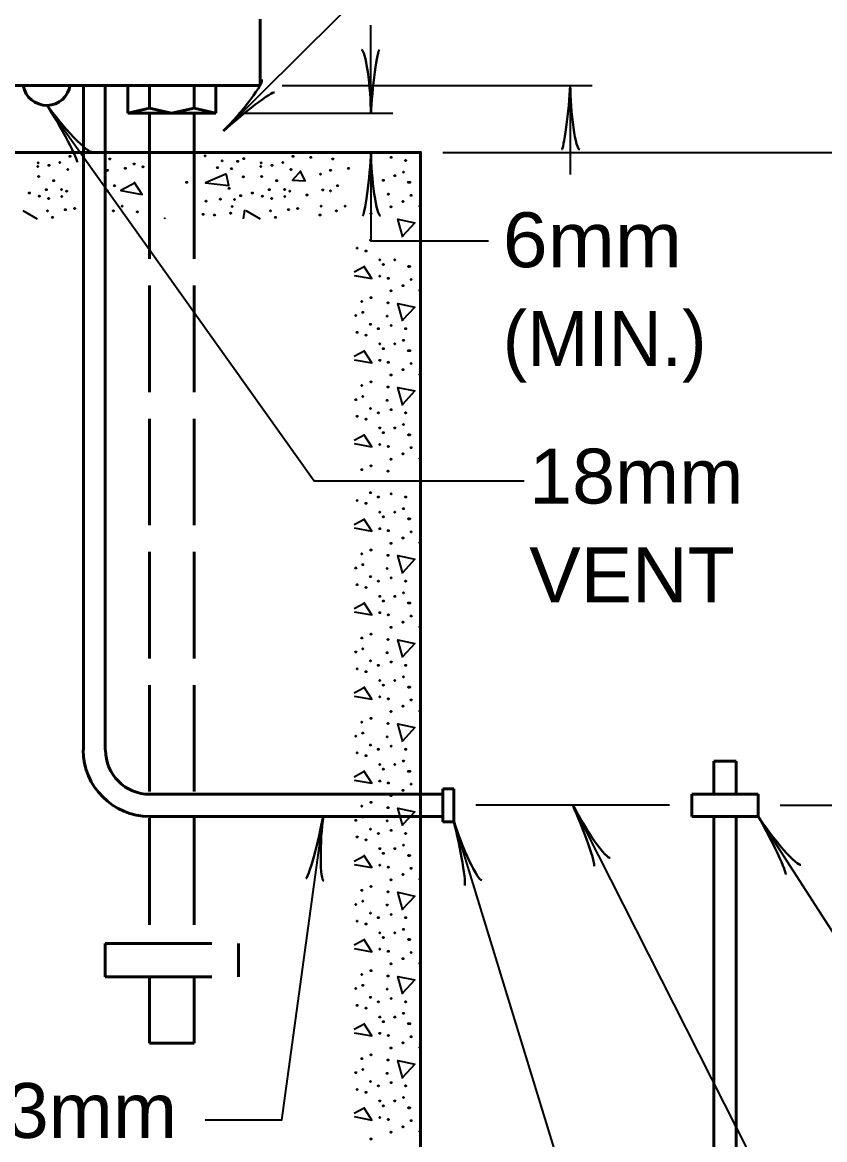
# Model space of a CAD drawing. Extents: x -39 to 816, y -16 to 528.
# Drawn here: x 272.5 to 316.4, y 202.8 to 263.8 of the extents above; entities that cross this region are included whole.
import ezdxf

# ---------------------------------------------------------------- set-up
doc = ezdxf.new("R2010")
doc.units = 0
doc.header["$LTSCALE"] = 0.97
doc.linetypes.add('LONG_DASHED', pattern=[7.5, 6, -1.5])
doc.layers.add('1', color=7, linetype='Continuous', lineweight=35)

msp = doc.modelspace()

# ---------------------------------------------------------------- linework, layer by layer
at = {"layer": '1', "lineweight": 53}
for p, q in [((285.5174, 263.9716), (285.5174, 260.3476)), ((258.3014, 260.3476), (285.5174, 260.3476)), ((275.8454, 260.3476), (275.8454, 224.0596)), ((277.0454, 260.3476), (277.0454, 224.0596)), ((278.2694, 260.3476), (278.2694, 258.8356)), ((279.4694, 260.3476), (279.4694, 259.1236)), ((281.8934, 260.3476), (281.8934, 259.1236)), ((283.0934, 260.3476), (283.0934, 258.8356)), ((278.2694, 258.8356), (279.4694, 259.1236)), ((278.2694, 258.8356), (283.0934, 258.8356)), ((280.6694, 258.8356), (279.4694, 259.1236)), ((279.4694, 258.8356), (279.4694, 256.6996)), ((280.6694, 258.8356), (281.8934, 259.1236)), ((283.0934, 258.8356), (281.8934, 259.1236)), ((281.8934, 258.8356), (281.8934, 256.6996)), ((310.3094, 223.4356), (311.5334, 223.4356)), ((310.3094, 223.4356), (310.3094, 221.6356)), ((311.5334, 223.4356), (311.5334, 221.6356)), ((279.4694, 221.6356), (295.5014, 221.6356)), ((295.5014, 221.9236), (295.5014, 220.1236)), ((295.5014, 221.9236), (296.1014, 221.9236)), ((296.1014, 221.9236), (296.1014, 220.1236)), ((309.1094, 220.4116), (309.1094, 221.6356)), ((309.1094, 221.6356), (312.7334, 221.6356)), ((312.7334, 220.4116), (312.7334, 221.6356)), ((279.4694, 220.4116), (295.5014, 220.4116)), ((309.1094, 220.4116), (312.7334, 220.4116)), ((310.3094, 220.4116), (310.3094, 170.2276)), ((311.5334, 220.4116), (311.5334, 169.6276)), ((295.5014, 220.1236), (296.1014, 220.1236))]:
    msp.add_line(p, q, dxfattribs=at)
at = {"layer": '1'}
for p, q in [((291.5654, 258.8356), (291.5654, 263.6596)), ((286.7174, 260.3476), (303.6614, 260.3476)), ((302.4614, 260.3476), (302.4614, 255.4996)), ((284.3174, 258.8356), (292.7654, 258.8356)), ((281.1254, 256.6756), (281.1014, 256.6996)), ((291.5654, 256.6996), (291.5654, 251.8756)), ((293.3174, 256.6756), (293.2934, 256.6996)), ((295.5014, 256.6996), (324.2451, 256.6996)), ((272.5334, 253.5316), (273.3254, 253.0756)), ((284.6054, 253.0756), (284.6774, 253.5556)), ((284.7254, 253.5316), (285.5174, 253.0756)), ((291.5654, 251.8756), (297.9974, 251.8756)), ((291.2294, 250.4596), (290.6534, 250.1476)), ((291.2294, 245.8516), (290.6534, 245.5396)), ((291.2294, 241.2676), (290.6534, 240.9556)), ((291.2294, 236.6596), (290.6534, 236.3476)), ((291.2294, 232.0756), (290.6534, 231.7636)), ((291.2294, 227.4676), (290.6534, 227.1556)), ((291.2294, 222.8836), (290.6534, 222.5716)), ((307.8854, 221.0356), (297.3014, 221.0356)), ((313.9334, 221.0356), (324.2451, 221.0356)), ((291.2294, 218.2756), (290.6534, 217.9636)), ((291.2294, 213.6916), (290.6534, 213.3796)), ((291.2294, 209.0836), (290.6534, 208.7716)), ((291.2294, 204.4996), (290.6534, 204.1876))]:
    msp.add_line(p, q, dxfattribs=at)
at = {"layer": '1', "linetype": 'LONG_DASHED', "lineweight": 53}
for p, q in [((279.4694, 256.6996), (279.4694, 213.4756)), ((281.8934, 256.6996), (281.8934, 213.4756)), ((277.0454, 213.4756), (284.3174, 213.4756)), ((277.0454, 213.4756), (277.0454, 211.6516)), ((284.3174, 213.4756), (284.3174, 211.6516)), ((277.0454, 211.6516), (284.3174, 211.6516)), ((279.4694, 211.6516), (279.4694, 208.0276)), ((281.8934, 211.6516), (281.8934, 208.0276)), ((279.4694, 208.0276), (281.8934, 208.0276))]:
    msp.add_line(p, q, dxfattribs=at)
at = {"layer": '1'}
for points in [[(283.5072, 257.8762), (300.1083, 274.3443), (323.9155, 274.3443)], [(273.8534, 259.2676), (288.4694, 238.7476), (299.9414, 238.7476)], [(283.6694, 255.5236), (282.5174, 255.0436), (283.7894, 254.8996), (283.6694, 255.4756)], [(287.7254, 255.6916), (287.2694, 255.1876), (287.9654, 255.1396), (287.7254, 255.6436)], [(278.6774, 255.0436), (277.8854, 254.6116), (279.0614, 254.3956), (278.6294, 255.0676)], [(293.3174, 252.0676), (293.0294, 253.0516), (293.9654, 252.8596), (293.2934, 252.1156)], [(290.6534, 249.9796), (291.6134, 249.8116), (291.1814, 250.4836)], [(293.3174, 247.4836), (293.0294, 248.4436), (293.9654, 248.2516), (293.2934, 247.5316)], [(290.6534, 245.3716), (291.6134, 245.2036), (291.1814, 245.8756)], [(293.3174, 242.8756), (293.0294, 243.8596), (293.9654, 243.6676), (293.2934, 242.9236)], [(290.6534, 240.7876), (291.6134, 240.6196), (291.1814, 241.2916)], [(290.6534, 236.1796), (291.6134, 236.0116), (291.1814, 236.6836)], [(293.3174, 233.6836), (293.0294, 234.6676), (293.9654, 234.4756), (293.2934, 233.7316)], [(290.6534, 231.5956), (291.6134, 231.4276), (291.1814, 232.0996)], [(293.3174, 229.0996), (293.0294, 230.0596), (293.9654, 229.8676), (293.2934, 229.1476)], [(290.6534, 226.9876), (291.6134, 226.8196), (291.1814, 227.4916)], [(293.3174, 224.4916), (293.0294, 225.4756), (293.9654, 225.2836), (293.2934, 224.5396)], [(290.6534, 222.4036), (291.6134, 222.2356), (291.1814, 222.9076)], [(302.6054, 221.0356), (316.3814, 193.8676), (326.9174, 193.8676)], [(288.9494, 220.4116), (286.6694, 203.8276), (282.4957, 203.8276)], [(293.3174, 219.9076), (293.0294, 220.8676), (293.9654, 220.6756), (293.2934, 219.9556)], [(312.7334, 220.4116), (320.5574, 208.2916), (326.9174, 208.2916)], [(296.1014, 220.1236), (307.2854, 183.6196), (326.9174, 183.6196)], [(290.6534, 217.7956), (291.6134, 217.6276), (291.1814, 218.2996)], [(293.3174, 215.2996), (293.0294, 216.2836), (293.9654, 216.0676), (293.2934, 215.3476)], [(290.6534, 213.2116), (291.6134, 213.0196), (291.1814, 213.7156)], [(293.3174, 210.7156), (293.0294, 211.6756), (293.9654, 211.4836), (293.2934, 210.7636)], [(290.6534, 208.6036), (291.6134, 208.4356), (291.1814, 209.1076)], [(293.3174, 206.1076), (293.0294, 207.0916), (293.9654, 206.8756), (293.2934, 206.1556)], [(290.6534, 204.0196), (291.6134, 203.8276), (291.1814, 204.5236)]]:
    msp.add_lwpolyline(points, dxfattribs=at)
at = {"layer": '1', "lineweight": 53}
msp.add_lwpolyline([(249.5414, 182.9236), (249.5414, 256.6996), (294.2774, 256.6996), (294.2774, 179.2996)], dxfattribs=at)
at = {"layer": '1'}
for centre in [(275.1113, 256.4824), (282.5016, 256.5145), (287.3041, 256.4824), (288.282, 256.4343), (292.6745, 256.4343), (273.3547, 255.927), (273.3708, 256.1296), (273.9639, 255.9911), (274.557, 256.1456), (274.9991, 255.7666), (277.2916, 256.3381), (278.1412, 255.8308), (278.6221, 256.0655), (279.103, 255.9109), (283.1749, 255.8629), (283.4314, 256.2419), (283.9444, 255.8147), (284.2811, 256.2098), (284.6177, 256.354), (285.5475, 255.927), (285.5635, 256.1296), (286.1566, 255.9911), (286.7498, 256.1456), (287.1919, 255.7666), (289.4843, 256.3381), (290.334, 255.8308), (293.46, 256.2578), (273.4028, 255.3818), (274.2204, 255.1573), (277.1633, 255.7185), (284.5856, 255.3657), (285.5956, 255.3818), (286.4132, 255.1573), (288.811, 255.5101), (289.3561, 255.7185), (292.2416, 255.1733), (292.8668, 255.4299), (293.3478, 255.6224), (273.8196, 254.6602), (274.6533, 254.6762), (274.935, 254.58), (277.1633, 254.596), (277.548, 254.8847), (281.4917, 255.0611), (283.8161, 254.7403), (286.0123, 254.6602), (286.846, 254.6762), (287.1278, 254.58), (288.9392, 254.6441), (289.3561, 254.596), (289.7408, 254.8847), (293.6203, 255.0611), (293.6844, 255.0611), (272.8898, 254.4838), (273.4349, 254.3074), (273.9479, 254.179), (274.6692, 254.2913), (282.5497, 254.0348), (283.3352, 254.147), (284.1047, 254.131), (284.4413, 254.3394), (285.0825, 254.4838), (285.6277, 254.3074), (286.1407, 254.179), (286.862, 254.2913), (288.0735, 254.3715), (292.5141, 254.4197), (293.3157, 254.0187), (293.7646, 254.3554), (273.8837, 253.5056), (274.8617, 253.5697), (275.3678, 253.6338), (277.4839, 253.5056), (277.9648, 253.7622), (278.7978, 253.4501), (282.3894, 253.3132), (283.8963, 253.3773), (283.9765, 253.7461), (286.0765, 253.5056), (287.0544, 253.5697), (287.5605, 253.6338), (288.843, 253.7622), (289.6767, 253.5056), (290.1576, 253.7622), (291.5683, 253.3612), (292.6584, 253.73), (294.2455, 253.7622), (274.1563, 253.1527), (283.0145, 253.2811), (286.3491, 253.1527), (288.779, 253.2811), (291.5363, 251.9019), (290.8149, 251.469), (291.2958, 251.3144), (292.0492, 250.8334), (292.2416, 250.5768), (292.8668, 250.8334), (293.6203, 250.4646), (293.6844, 250.4646), (292.0493, 249.9353), (292.5141, 249.8232), (293.7646, 249.759), (292.6584, 249.1336), (293.3157, 249.4222), (294.2455, 249.1657), (291.0713, 248.5562), (291.5683, 248.7647), (292.4981, 248.4761), (291.1195, 247.963), (290.7347, 247.7866), (291.5363, 247.3055), (292.45, 247.7545), (292.6745, 247.2414), (290.8149, 246.8725), (291.2958, 246.718), (291.9691, 247.0649), (293.46, 247.0649), (292.0492, 246.237), (292.8668, 246.237), (293.3478, 246.4294), (292.2416, 245.9803), (293.6203, 245.8681), (293.6844, 245.8681), (292.0493, 245.3389), (292.5141, 245.2267), (293.3157, 244.8258), (293.7646, 245.1625), (291.5683, 244.1683), (292.6584, 244.5371), (294.2455, 244.5692), (291.0713, 243.9598), (292.4981, 243.8796), (290.7347, 243.1901), (291.1195, 243.3665), (292.45, 243.158), (291.5363, 242.709), (291.9691, 242.4684), (292.6745, 242.6449), (293.46, 242.4684), (290.8149, 242.276), (291.2958, 242.1215), (293.3478, 241.8329), (292.0492, 241.6405), (292.2416, 241.3838), (292.8668, 241.6405), (293.6203, 241.2717), (293.6844, 241.2717), (292.0493, 240.7424), (292.5141, 240.6302), (293.7646, 240.566), (292.6584, 239.9406), (293.3157, 240.2293), (294.2455, 239.9727), (291.0713, 239.3633), (291.5683, 239.5718), (292.4981, 239.2831), (291.5363, 238.1125), (292.6745, 238.0484), (290.8149, 237.6796), (291.2958, 237.525), (291.9691, 237.8719), (293.46, 237.8719), (292.0492, 237.044), (292.8668, 237.044), (293.3478, 237.2364), (292.2416, 236.7873), (293.6203, 236.6752), (293.6844, 236.6752), (292.0493, 236.1459), (292.5141, 236.0337), (293.3157, 235.6328), (293.7646, 235.9695), (292.6584, 235.3441), (294.2455, 235.3762), (291.0713, 234.7668), (291.5683, 234.9753), (292.4981, 234.6866), (290.7347, 233.9971), (291.1195, 234.1735), (292.45, 233.965), (291.5363, 233.516), (291.9691, 233.2754), (292.6745, 233.4519), (293.46, 233.2754), (290.8149, 233.0831), (291.2958, 232.9285), (293.3478, 232.64), (292.0492, 232.4475), (292.2416, 232.1909), (292.8668, 232.4475), (293.6203, 232.0787), (293.6844, 232.0787), (292.0493, 231.5494), (292.5141, 231.4373), (293.7646, 231.373), (292.6584, 230.7476), (293.3157, 231.0363), (294.2455, 230.7798), (291.0713, 230.1703), (291.5683, 230.3788), (291.1195, 229.577), (292.4981, 230.0902), (290.7347, 229.4007), (291.5363, 228.9195), (292.45, 229.3685), (290.8149, 228.4866), (291.2958, 228.332), (291.9691, 228.6789), (292.6745, 228.8554), (293.46, 228.6789), (292.0492, 227.851), (292.8668, 227.851), (293.3478, 228.0435), (292.2416, 227.5944), (293.6203, 227.4822), (293.6844, 227.4822), (292.0493, 226.9529), (292.5141, 226.8408), (293.7646, 226.7766), (292.6584, 226.1512), (293.3157, 226.4398), (294.2455, 226.1833), (291.0713, 225.5738), (291.5683, 225.7823), (292.4981, 225.4937), (290.7347, 224.8042), (291.1195, 224.9806), (292.45, 224.7721), (291.5363, 224.3231), (291.9691, 224.0825), (292.6745, 224.259), (293.46, 224.0825), (290.8149, 223.8901), (291.2958, 223.7356), (293.3478, 223.447), (292.0492, 223.2546), (292.2416, 222.9979), (292.8668, 223.2546), (293.6203, 222.8857), (293.6844, 222.8857), (292.0493, 222.3565), (292.5141, 222.2443), (293.7646, 222.1801), (293.3157, 221.8434), (294.2455, 221.5868), (291.0713, 220.9774), (291.5683, 221.1859), (292.6584, 221.5547), (291.1195, 220.3841), (292.4981, 220.8972), (290.7347, 220.2077), (292.45, 220.1756), (290.8149, 219.2936), (291.2958, 219.1391), (291.5363, 219.7266), (291.9691, 219.486), (292.6745, 219.6625), (293.46, 219.486), (292.0492, 218.6581), (292.8668, 218.6581), (293.3478, 218.8505), (292.2416, 218.4014), (293.6203, 218.2893), (293.6844, 218.2893), (292.0493, 217.76), (292.5141, 217.6478), (293.7646, 217.5836), (292.6584, 216.9582), (293.3157, 217.2469), (294.2455, 216.9903), (291.0713, 216.3809), (291.5683, 216.5894), (292.4981, 216.3007), (290.7347, 215.6112), (291.1195, 215.7876), (292.45, 215.5791), (291.5363, 215.1301), (291.9691, 214.8895), (292.6745, 215.066), (293.46, 214.8895), (290.8149, 214.6972), (291.2958, 214.5426), (293.3478, 214.254), (292.0492, 214.0616), (292.2416, 213.8049), (292.8668, 214.0616), (293.6203, 213.6928), (293.6844, 213.6928), (292.0493, 213.1635), (292.5141, 213.0513), (293.3157, 212.6504), (293.7646, 212.9871), (291.5683, 211.9929), (292.6584, 212.3617), (294.2455, 212.3938), (291.0713, 211.7844), (291.1195, 211.1911), (292.4981, 211.7042), (290.7347, 211.0147), (292.45, 210.9826), (290.8149, 210.1007), (291.5363, 210.5336), (291.9691, 210.293), (292.6745, 210.4695), (293.46, 210.293), (291.2958, 209.9461), (292.0492, 209.4651), (292.8668, 209.4651), (293.3478, 209.6576), (292.2416, 209.2085), (293.6203, 209.0963), (293.6844, 209.0963), (292.0493, 208.567), (292.5141, 208.4549), (293.7646, 208.3906), (292.6584, 207.7652), (293.3157, 208.0539), (294.2455, 207.7974), (291.0713, 207.1879), (291.5683, 207.3964), (292.4981, 207.1078), (290.7347, 206.4183), (291.1195, 206.5946), (292.45, 206.3861), (291.5363, 205.9371), (291.9691, 205.6965), (292.6745, 205.873), (293.46, 205.6965), (290.8149, 205.5042), (291.2958, 205.3496), (292.0492, 204.8686), (292.2416, 204.612), (292.8668, 204.8686), (293.3478, 205.0611), (293.6203, 204.4998), (293.6844, 204.4998), (292.0493, 203.9705), (292.5141, 203.8584), (293.3157, 203.4574), (293.7646, 203.7942), (291.5683, 202.7999), (292.6584, 203.1688), (294.2455, 203.2009)]:
    msp.add_circle(centre, 0.032, dxfattribs=at)
at = {"layer": '1', "lineweight": 53}
for centre, radius, start, end in [((273.8384, 260.5724), 1.3014, 190.44188, 351.63642), ((279.4716, 224.0486), 3.6288, 180, 270), ((279.4716, 224.0486), 2.4192, 180, 270)]:
    msp.add_arc(centre, radius, start, end, dxfattribs=at)
at = {"layer": '1'}
for centre, start, end in [((273.7235, 256.7389), 256.94318, 283.05682), ((273.996, 256.7389), 256.94318, 283.05682), ((285.9162, 256.7389), 256.94318, 283.05682), ((286.1887, 256.7389), 256.94318, 283.05682), ((294.2936, 255.7506), 97.86167, 262.13833), ((280.3053, 253.0726), 11.5283, 168.4717), ((294.2936, 251.1541), 97.86167, 262.13833), ((294.2936, 246.5576), 97.86167, 262.13833), ((294.2936, 241.9612), 97.86167, 262.13833), ((294.2936, 237.3647), 97.86167, 262.13833), ((294.2936, 232.7682), 97.86167, 262.13833), ((294.2936, 228.1717), 97.86167, 262.13833), ((294.2936, 223.5752), 97.86167, 262.13833), ((294.2936, 218.9788), 97.86167, 262.13833), ((294.2936, 214.3823), 97.86167, 262.13833), ((294.2936, 209.7858), 97.86167, 262.13833), ((294.2936, 205.1893), 97.86167, 262.13833)]:
    msp.add_arc(centre, 0.032, start, end, dxfattribs=at)
at = {"layer": '1', "lineweight": 40}
for centre, major_axis, ratio, start_param, end_param in [((291.2334, 260.1445), (0.1889, -2.16), 0.122415, 0.8963533, 3.1415927), ((291.8235, 260.1799), (-0.2125, -2.1246), 0.07063, 3.1407148, 5.41811), ((284.2033, 259.0338), (-1.3893, -1.6421), 0.122415, 0.8963533, 3.1415927), ((302.198, 258.9812), (0.2125, 2.1246), 0.07063, 3.1407148, 5.41811), ((302.7882, 259.0166), (-0.1889, 2.16), 0.122415, 0.8963533, 3.1415927), ((284.6406, 258.6429), (-1.6448, -1.3348), 0.07063, 3.1407148, 5.41811), ((274.4392, 258.0184), (1.0585, -1.8544), 0.07063, 6.2823074, 8.5597026), ((274.8995, 258.3894), (-1.406, 1.6505), 0.122415, 0.8963533, 3.1415927), ((291.3116, 255.3524), (0.2125, 2.1246), 0.07063, 3.1407148, 5.41811), ((291.9018, 255.3878), (-0.1889, 2.16), 0.122415, 0.8963533, 3.1415927), ((302.99, 219.7), (0.7715, -1.9909), 0.07063, 6.2823074, 8.5597026), ((302.99, 219.7), (0.7715, -1.9909), 0.07063, 6.2823074, 8.5597026), ((303.5003, 219.9985), (-1.1454, 1.841), 0.122415, 0.8963533, 3.1415927), ((303.5003, 219.9985), (-1.1454, 1.841), 0.122415, 0.8963533, 3.1415927), ((288.5145, 219.1121), (0.5007, 2.0757), 0.07063, 3.1407148, 5.41811), ((289.1039, 219.0666), (0.1079, 2.1655), 0.122415, 0.8963533, 3.1415927), ((313.2556, 219.1422), (0.9737, -1.9003), 0.07063, 6.2823074, 8.5597026), ((313.7322, 219.492), (-1.3301, 1.7123), 0.122415, 0.8963533, 3.1415927), ((296.2561, 218.7465), (0.4196, -2.0936), 0.07063, 6.2823074, 8.5597026), ((296.2561, 218.7465), (0.4196, -2.0936), 0.07063, 6.2823074, 8.5597026), ((296.81, 218.9534), (-0.8137, 2.0098), 0.122415, 0.8963533, 3.1415927), ((296.81, 218.9534), (-0.8137, 2.0098), 0.122415, 0.8963533, 3.1415927)]:
    msp.add_ellipse(centre, major_axis=major_axis, ratio=ratio, start_param=start_param, end_param=end_param, dxfattribs=at)

# ---------------------------------------------------------------- texts
at = {"layer": '1'}
for s, width, p in [('6mm', 1.1, (298.7703, 250.426)), ('18mm', 1.05, (300.22, 237.514)), ('VENT', 1.05, (300.22, 232.114)), ('13mm', 1.05, (269.2658, 202.8533))]:
    msp.add_text(s, height=3, dxfattribs=dict(at, width=width)).set_placement(p)
msp.add_text('(MIN.)', height=3, dxfattribs=at).set_placement((298.7703, 245.026))

doc.saveas('drawing.dxf')
